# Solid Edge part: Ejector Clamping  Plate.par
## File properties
Author: Dan
Template: metric part.par
Last saved by: Dan
Revision: 21
Application: Solid Edge
Material: Steel
Face Style: Steel
Fill Style: ANSI32(Steel)
Virtual Style: Machined steel
Coef. of Thermal Exp: 1.3e-05
Thermal Conductivity: 32.0
Specific Heat: 481.0
Modulus of Elasticity: 199947953000.0
Poisson's Ratio: 0.29
Yield Stress: 262000766.0
Ultimate Stress: 358527364.0
Elongation: 0.0
Density: 7833.000 kg/m^3
Accuracy: 0.990
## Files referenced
..\Wheel Mould.asm
C:\Drawing Files Other\Dave\Tente\HUP 125X36H45-TSA 02-07-2011\Wheel Mould\Ejector Plate.par
ZC:\Drawing Files Other\Dave\Tente\HUP 125X36H45-TSA 02-07-2011\Wheel Mould\Wheel Mould.asm
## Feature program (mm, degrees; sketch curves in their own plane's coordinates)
sketch for "unnamed Protrusion 1" plane through (0, 0, 0) normal (0, 0, 1) x-axis (1, 0, 0)
extrude "unnamed Protrusion 1" add finite 26 along -normal
sketch for "Hole_9" plane through (0, 0, 0) normal (0, 0, 1) x-axis (1, 0, 0)
hole "Hole_9" diameter 8.5 through  CounterBoreDepth = 8.5 mm
sketch for "unnamed Hole 1" plane through (0, 0, 0) normal (0, 0, 1) x-axis (1, 0, 0)
hole "unnamed Hole 1" through
sketch for "unnamed Hole 2" plane through (0, 0, 0) normal (0, 0, 1) x-axis (1, 0, 0)
hole "unnamed Hole 2" through
sketch for "unnamed Hole 3" plane through (0, 0, 0) normal (0, 0, 1) x-axis (1, 0, 0)
  hole centre (128, -180) bore radius 4.25
hole "unnamed Hole 3" through
pattern "unnamed Pattern 1" of "Hole_9", "unnamed Hole 1", "unnamed Hole 2", "unnamed Hole 3"
sketch for "Hole_13" plane through (0, 0, 0) normal (0, 0, 1) x-axis (1, 0, 0)
hole "Hole_13" diameter 10 through  VBottomAngle = 118 deg
sketch for "unnamed Cutout 1" #1 plane through (0, 0, 0) normal (0, 0, 1) x-axis (-1, 0, 0)
sketch for "unnamed Cutout 1" #2 plane through (0, 0, 0) normal (0, 0, 1) x-axis (-1, 0, 0)
extrude "unnamed Cutout 1" cut through along -normal
sketch for "Hole_14" plane through (0, 0, 0) normal (0, 0, 1) x-axis (-1, 0, 0)
hole "Hole_14" diameter 33 through  VBottomAngle = 118 deg
sketch for "unnamed Hole 4" plane through (0, 0, 0) normal (0, 0, 1) x-axis (-1, 0, 0)
  hole centre (75, 75) bore radius 16.5
hole "unnamed Hole 4" through
sketch for "unnamed Hole 5" plane through (0, 0, 0) normal (0, 0, 1) x-axis (-1, 0, 0)
  hole centre (75, -75) bore radius 16.5
hole "unnamed Hole 5" through
sketch for "unnamed Hole 6" plane through (0, 0, 0) normal (0, 0, 1) x-axis (-1, 0, 0)
  hole centre (-75, -75) bore radius 16.5
hole "unnamed Hole 6" through
pattern "unnamed Pattern 2" of "Hole_14", "unnamed Hole 4", "unnamed Hole 5", "unnamed Hole 6"
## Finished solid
Body 1: solid body, 25 faces, 42 edges, 8 vertices.
  Faces by surface: cylinder 15, plane 10
  Edges by curve: circle 30, line 12
Bounding box of the edges (mm): 280.000 x 396.000 x 26.000, from (-140, -198, -26) to (140, 198, 0).
Cylindrical faces by radius (mm): R4.188 x1, R4.25 x4, R7.5 x4, R16.5 x4, R36 x2
Planar faces by outward normal: +x 1, +y 1, +z 5, -x 1, -y 1, -z 1
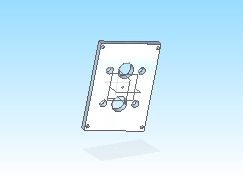
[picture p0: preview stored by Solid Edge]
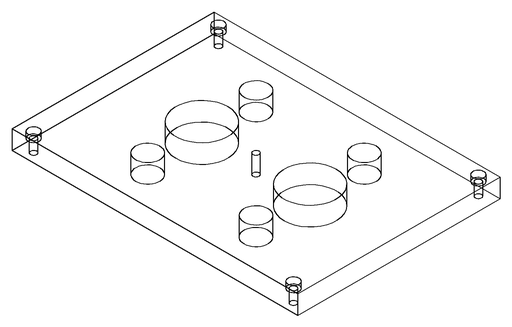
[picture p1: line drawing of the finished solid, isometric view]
